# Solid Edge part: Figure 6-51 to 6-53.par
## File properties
Author: CADCIM
Template: normal.par
Last saved by: CADCIM
Revision: 6
Application: Solid Edge
Accuracy: 0.99
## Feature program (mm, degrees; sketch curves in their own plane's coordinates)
sketch for "unnamed RevolvedProtrusion 1" plane through (0, 0, 0) normal (1, 0, 0) x-axis (0, 1, 0)
  line (0, 0) -> (0, 61.0971)
  line (0, 61.0971) -> (-17.5608, 61.0971)
  line (-17.5608, 61.0971) -> (-17.5608, 58.5636)
  line (-17.5608, 58.5636) -> (-7.2757, 55.8892)
  line (-7.2757, 55.8892) -> (-7.2757, 18.8758)
  line (-7.2757, 18.8758) -> (-38.6275, 18.8758)
  line (-38.6275, 18.8758) -> (-38.6275, 0)
  line (0, 0) -> (-38.6275, 0)
revolve "unnamed RevolvedProtrusion 1" add full turn 360 deg
sketch for "unnamed Hole 1" plane through (0, -38.6275, 0) normal (0, -1, 0) x-axis (1, 0, 0)
  hole centre (0, 0) bore radius 12
hole "unnamed Hole 1" through
sketch for "Hole_25" plane through (0, -7.2757, 0) normal (0, -1, 0) x-axis (1, 0, 0)
  hole centre (0, -43.8984) bore radius 6
hole "Hole_25" diameter 12 through
pattern "unnamed Pattern 1" of "Hole_25"
pattern "unnamed Pattern 2"
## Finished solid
Body 1: solid body, 18 faces, 28 edges, 0 vertices.
  Faces by surface: cylinder 13, plane 4, cone 1
  Edges by curve: circle 28
Bounding box of the edges (mm): 122.194 x 38.627 x 122.194, from (-61.0971, -38.6275, -61.0971) to (61.0971, 0, 61.0971).
Cylindrical faces by radius (mm): R6 x10, R12 x1, R18.8758 x1, R61.0971 x1
Conical faces (half-angle, radius in mm at the cone's reference point): 14.5755 deg R58.5636 x1
Planar faces by outward normal: +y 1, -y 3
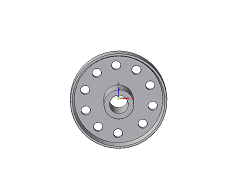
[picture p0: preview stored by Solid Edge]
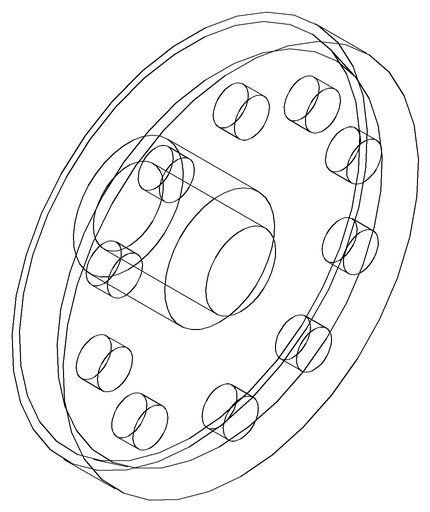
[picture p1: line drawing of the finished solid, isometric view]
